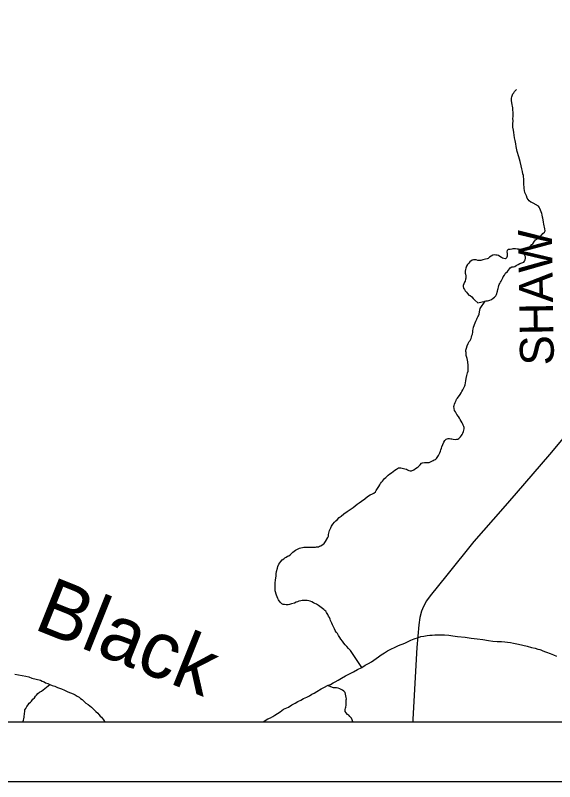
# Model space of a CAD drawing. Extents: x 10.6 to 44.6, y -2.6 to 23.4.
# Drawn here: x 14.367 to 15.273, y 15.426 to 16.714 of the extents above; entities that cross this region are included whole.
import ezdxf

# ---------------------------------------------------------------- set-up
doc = ezdxf.new("R2010")
doc.units = 0
for name, color, linetype in [('GM_X_County', 7, 'Continuous'), ('GM_X_Minor_Lake', 7, 'Continuous'), ('GM_X_Minor_River', 7, 'Continuous'), ('GM_X_Minor_River_Text', 7, 'Continuous'), ('GM_X_Township', 7, 'Continuous'), ('GM_X_Township_Road', 7, 'Continuous'), ('GM_X_Township_Road_Text', 7, 'Continuous'), ('SH_Data', 7, 'Continuous')]:
    doc.layers.add(name, color=color, linetype=linetype)

msp = doc.modelspace()

# ---------------------------------------------------------------- linework, layer by layer
at = {"layer": 'GM_X_County'}
msp.add_lwpolyline([(20.0033, 15.5302), (20.0033, 22.3267), (13.2033, 22.3267), (13.2033, 15.5267), (19.8413, 15.5267)], dxfattribs=at)
at = {"layer": 'GM_X_Minor_Lake'}
for points in [[(15.1779, 16.255), (15.1782, 16.2573), (15.1786, 16.2596), (15.1793, 16.2615), (15.1804, 16.2634), (15.1815, 16.2653), (15.1826, 16.2673), (15.1844, 16.2707), (15.1855, 16.2727), (15.1862, 16.2746), (15.1881, 16.2773), (15.1903, 16.2804), (15.1932, 16.2835), (15.1951, 16.2858), (15.1966, 16.2877), (15.198, 16.2897), (15.2007, 16.2913), (15.2033, 16.2913), (15.2056, 16.2918), (15.2082, 16.2933), (15.2116, 16.2953), (15.2142, 16.2969), (15.2173, 16.2977), (15.221, 16.299), (15.2221, 16.3009), (15.2229, 16.3028), (15.2236, 16.3055), (15.2235, 16.3082), (15.2227, 16.31), (15.2219, 16.3123), (15.2207, 16.3149), (15.2187, 16.3179), (15.2168, 16.319), (15.2141, 16.3201), (15.2118, 16.3208), (15.2095, 16.3211), (15.2068, 16.3215), (15.2049, 16.3214), (15.2026, 16.3214), (15.2008, 16.3209), (15.1977, 16.3205), (15.1947, 16.3204), (15.1928, 16.3185), (15.1925, 16.3162), (15.1926, 16.3135), (15.1926, 16.3112), (15.1927, 16.309), (15.192, 16.3063), (15.1901, 16.3047), (15.1874, 16.3054), (15.1851, 16.3058), (15.1832, 16.3068), (15.1805, 16.3087), (15.1782, 16.3102), (15.1759, 16.3109), (15.1736, 16.3108), (15.1709, 16.3111), (15.169, 16.3107), (15.166, 16.3091), (15.1634, 16.3075), (15.1612, 16.3052), (15.1593, 16.3048), (15.1566, 16.304), (15.154, 16.3035), (15.1517, 16.3031), (15.1487, 16.3019), (15.1468, 16.3018), (15.1437, 16.3021), (15.141, 16.3028), (15.1384, 16.3028), (15.1361, 16.3031), (15.1338, 16.3023), (15.1301, 16.2995), (15.1286, 16.2976), (15.126, 16.2949), (15.1245, 16.2922), (15.1235, 16.2887), (15.1228, 16.2868), (15.1225, 16.2838), (15.1221, 16.2807), (15.123, 16.2788), (15.1234, 16.2762), (15.1235, 16.2724), (15.1231, 16.2705), (15.1225, 16.2674), (15.1214, 16.2655), (15.1203, 16.2628), (15.1192, 16.2601), (15.1192, 16.2582), (15.1197, 16.2555), (15.1213, 16.2529), (15.1224, 16.251), (15.1248, 16.2488), (15.1264, 16.2462), (15.1283, 16.2439), (15.1306, 16.2429), (15.1337, 16.2406), (15.1357, 16.238), (15.1388, 16.2351), (15.1435, 16.231), (15.156, 16.2335)], [(15.156, 16.2335), (15.1578, 16.234), (15.1597, 16.234), (15.162, 16.2344), (15.1639, 16.2353), (15.1665, 16.2365), (15.1695, 16.2384), (15.1718, 16.24), (15.1736, 16.2423), (15.1751, 16.245), (15.1765, 16.2504), (15.1772, 16.2531), (15.1779, 16.255)]]:
    msp.add_lwpolyline(points, dxfattribs=at)
at = {"layer": 'GM_X_Minor_River'}
for points in [[(15.2187, 16.3179), (15.2322, 16.3262), (15.2341, 16.3286), (15.2359, 16.3301), (15.2385, 16.3344), (15.2407, 16.3363), (15.2437, 16.3387), (15.2456, 16.3402), (15.2482, 16.3418), (15.2512, 16.3449), (15.253, 16.3473), (15.2553, 16.3496), (15.2567, 16.3519), (15.2563, 16.3553), (15.2555, 16.358), (15.255, 16.3602), (15.2546, 16.3629), (15.2541, 16.3663), (15.2533, 16.3701), (15.2528, 16.3727), (15.2524, 16.3746), (15.2519, 16.3784), (15.2508, 16.3807), (15.2499, 16.3837), (15.2491, 16.3864), (15.2479, 16.3894), (15.2467, 16.3913), (15.2455, 16.3931), (15.2367, 16.3979), (15.2344, 16.399), (15.2324, 16.3997), (15.2297, 16.4023), (15.2281, 16.4041), (15.2266, 16.4068), (15.2253, 16.4106), (15.2237, 16.4139), (15.2225, 16.4162), (15.2221, 16.4196), (15.2216, 16.4226), (15.2216, 16.4257), (15.2211, 16.4287), (15.221, 16.4321), (15.221, 16.4352), (15.2209, 16.4371), (15.2209, 16.4394), (15.2204, 16.442), (15.22, 16.4447), (15.2192, 16.4477), (15.2187, 16.4515), (15.2174, 16.456), (15.2166, 16.4606), (15.2145, 16.4681), (15.2124, 16.4761), (15.2099, 16.4852), (15.2082, 16.4935), (15.2074, 16.498), (15.2065, 16.5033), (15.2052, 16.5079), (15.2044, 16.5124), (15.2039, 16.5166), (15.2034, 16.5208), (15.2025, 16.5257), (15.2024, 16.5314), (15.2027, 16.5364), (15.2026, 16.5402), (15.2029, 16.544), (15.2032, 16.5478), (15.2031, 16.5508), (15.2026, 16.5546), (15.2026, 16.5565), (15.2022, 16.5584), (15.2017, 16.5611), (15.2013, 16.5633), (15.2004, 16.5706), (15.2003, 16.5725), (15.2003, 16.5747), (15.2006, 16.5766), (15.2013, 16.5786), (15.2024, 16.5816), (15.2039, 16.5836), (15.2054, 16.5855), (15.2076, 16.5882), (15.2087, 16.589)], [(15.1184, 16.0116), (15.1195, 16.0147), (15.1202, 16.017), (15.1205, 16.0193), (15.1205, 16.0212), (15.1201, 16.0231), (15.1192, 16.025), (15.1181, 16.0272), (15.1173, 16.0291), (15.1157, 16.0321), (15.1141, 16.0347), (15.1125, 16.037), (15.1109, 16.0396), (15.1082, 16.0433), (15.107, 16.0456), (15.1058, 16.0479), (15.1046, 16.0501), (15.1038, 16.0535), (15.1033, 16.0565), (15.1036, 16.0585), (15.1044, 16.0608), (15.1054, 16.0634), (15.1069, 16.0665), (15.108, 16.0688), (15.1094, 16.0708), (15.1139, 16.077), (15.1153, 16.0793), (15.1168, 16.082), (15.1183, 16.0847), (15.1197, 16.087), (15.1208, 16.0893), (15.1215, 16.0912), (15.1223, 16.0931), (15.1226, 16.0962), (15.1232, 16.0996), (15.1239, 16.1034), (15.1249, 16.1088), (15.1264, 16.113), (15.1271, 16.1161), (15.1274, 16.1191), (15.1273, 16.1218), (15.1272, 16.1244), (15.1272, 16.1271), (15.1267, 16.1298), (15.1267, 16.1317), (15.1263, 16.1343), (15.1254, 16.1373), (15.125, 16.1392), (15.1238, 16.1423), (15.1237, 16.1445), (15.1237, 16.1472), (15.1236, 16.1491), (15.1236, 16.151), (15.1243, 16.1548), (15.1257, 16.1587), (15.1271, 16.1625), (15.129, 16.1656), (15.1308, 16.1675), (15.1323, 16.1706), (15.133, 16.1733), (15.1337, 16.176), (15.1344, 16.1783), (15.1351, 16.1813), (15.1354, 16.184), (15.1357, 16.1867), (15.1364, 16.1897), (15.1389, 16.1974), (15.1404, 16.2001), (15.1418, 16.2032), (15.1425, 16.2051), (15.1436, 16.207), (15.1447, 16.2089), (15.1458, 16.2116), (15.1465, 16.2154), (15.1468, 16.2185), (15.1475, 16.2212), (15.156, 16.2335)], [(14.8856, 15.8267), (14.8878, 15.8298), (14.8918, 15.8364), (14.8925, 15.839), (14.8929, 15.8417), (14.8932, 15.844), (14.8939, 15.8463), (14.8942, 15.8482), (14.8953, 15.8505), (14.8964, 15.8528), (14.8979, 15.8559), (14.9001, 15.859), (14.9027, 15.8621), (14.9053, 15.8648), (14.9075, 15.8664), (14.9109, 15.8699), (14.9142, 15.8726), (14.9187, 15.8762), (14.9239, 15.8801), (14.9307, 15.8848), (14.9341, 15.8872), (14.9374, 15.8895), (14.9408, 15.8923), (14.9445, 15.8946), (14.9483, 15.8978), (14.9535, 15.9017), (14.9584, 15.9052), (14.9629, 15.908), (14.9666, 15.91), (14.9689, 15.9112), (14.9715, 15.9135), (14.973, 15.9158), (14.9748, 15.9189), (14.977, 15.922), (14.9788, 15.9251), (14.9803, 15.9274), (14.9818, 15.9293), (14.9833, 15.9313), (14.9851, 15.9336), (14.987, 15.9356), (14.9888, 15.9375), (14.9911, 15.9395), (14.9929, 15.9414), (14.9955, 15.9437), (14.9985, 15.9453), (15.0012, 15.9477), (15.0042, 15.9496), (15.0068, 15.9512), (15.0087, 15.9524), (15.0105, 15.9536), (15.0143, 15.9537), (15.0163, 15.9533), (15.0189, 15.9526), (15.0212, 15.9519), (15.0235, 15.9512), (15.0255, 15.9501), (15.0278, 15.949), (15.0297, 15.9483), (15.032, 15.9484), (15.0361, 15.9504), (15.0387, 15.9523), (15.0414, 15.9539), (15.0432, 15.9551), (15.0451, 15.9567), (15.0466, 15.9586), (15.0488, 15.9613), (15.0507, 15.9621), (15.0541, 15.9626), (15.0571, 15.9623), (15.0598, 15.9623), (15.0617, 15.9624), (15.064, 15.9636), (15.0662, 15.9648), (15.0685, 15.966), (15.0704, 15.9668), (15.0722, 15.9676), (15.0741, 15.9691), (15.0763, 15.9726), (15.0774, 15.9745), (15.0785, 15.9765), (15.0796, 15.9788), (15.0807, 15.9815), (15.0814, 15.9841), (15.0825, 15.9864), (15.0832, 15.9891), (15.0864, 15.9968), (15.0879, 15.9995), (15.0905, 16.0018), (15.0939, 16.0027), (15.0962, 16.0027), (15.0981, 16.0024), (15.1, 16.0021), (15.1023, 16.0017), (15.1053, 16.0014), (15.108, 16.0015), (15.1099, 16.0019), (15.1118, 16.0027), (15.1147, 16.0058), (15.1162, 16.0078), (15.1173, 16.0097), (15.1184, 16.0116)], [(14.949, 15.6185), (14.9297, 15.647), (14.9265, 15.6503), (14.9234, 15.6533), (14.9207, 15.6563), (14.9183, 15.6593), (14.916, 15.6623), (14.9136, 15.6656), (14.9117, 15.6686), (14.9097, 15.672), (14.9077, 15.6754), (14.9057, 15.6776), (14.9042, 15.6802), (14.903, 15.6829), (14.9006, 15.6874), (14.8994, 15.69), (14.8982, 15.6927), (14.8974, 15.6949), (14.8962, 15.6972), (14.8954, 15.6995), (14.8942, 15.7021), (14.893, 15.7043), (14.8918, 15.707), (14.8906, 15.7089), (14.8894, 15.7107), (14.8882, 15.7126), (14.8863, 15.7141), (14.8847, 15.7159), (14.8762, 15.7226), (14.8727, 15.7244), (14.87, 15.7259), (14.8673, 15.727), (14.8646, 15.7284), (14.8619, 15.7295), (14.8596, 15.7302), (14.857, 15.7305), (14.8535, 15.7308), (14.8516, 15.7308), (14.8486, 15.7307), (14.8463, 15.7303), (14.8429, 15.7295), (14.8407, 15.7286), (14.8384, 15.7278), (14.8354, 15.7262), (14.8305, 15.725), (14.8271, 15.7241), (14.8248, 15.7237), (14.8217, 15.7236), (14.8191, 15.724), (14.8164, 15.7243), (14.8141, 15.7254), (14.8114, 15.728), (14.809, 15.7317), (14.8078, 15.7344), (14.8066, 15.737), (14.8054, 15.7396), (14.8033, 15.7468), (14.8032, 15.7514), (14.8031, 15.7556), (14.8034, 15.7605), (14.8037, 15.7651), (14.8046, 15.7723), (14.805, 15.7758), (14.8056, 15.7792), (14.807, 15.785), (14.8077, 15.7876), (14.8091, 15.7918), (14.811, 15.7942), (14.8125, 15.7965), (14.8151, 15.7988), (14.8177, 15.8008), (14.8196, 15.8024), (14.8218, 15.8036), (14.8241, 15.8051), (14.8263, 15.8059), (14.8282, 15.8075), (14.8304, 15.8095), (14.8327, 15.8118), (14.8353, 15.8138), (14.8375, 15.8153), (14.8398, 15.8165), (14.8417, 15.8177), (14.8443, 15.8189), (14.8462, 15.8193), (14.8488, 15.8198), (14.8515, 15.8202), (14.8553, 15.8203), (14.8591, 15.8204), (14.8641, 15.8201), (14.8682, 15.8202), (14.8709, 15.8203), (14.8728, 15.8207), (14.8758, 15.8211), (14.8777, 15.8219), (14.8796, 15.8228), (14.8837, 15.8255), (14.8856, 15.8267)], [(14.7829, 15.5267), (14.7866, 15.5292), (14.7911, 15.5319), (14.7953, 15.5339), (14.799, 15.5359), (14.8028, 15.5379), (14.8069, 15.5407), (14.8118, 15.5438), (14.8174, 15.5481), (14.8257, 15.5517), (14.8313, 15.5553), (14.8366, 15.5581), (14.8414, 15.5609), (14.8463, 15.5636), (14.8508, 15.566), (14.8561, 15.5684), (14.8606, 15.5708), (14.8648, 15.5732), (14.8685, 15.5752), (14.873, 15.5779), (14.8805, 15.5823), (14.8858, 15.5851), (14.8911, 15.5879), (14.896, 15.5899), (14.9005, 15.5923), (14.9042, 15.5943), (14.9091, 15.597), (14.9147, 15.6002), (14.9211, 15.6042), (14.9279, 15.6074), (14.9347, 15.6109), (14.9414, 15.6149), (14.949, 15.6185), (14.9546, 15.622), (14.9602, 15.6252), (14.9647, 15.628), (14.9688, 15.6307), (14.9726, 15.6335), (14.9767, 15.6362), (14.9812, 15.6394), (14.9868, 15.6426), (14.9921, 15.6461), (14.9973, 15.6489), (15.0049, 15.6525), (15.0101, 15.6553), (15.0207, 15.6593), (15.0312, 15.6641), (15.0369, 15.6665), (15.0441, 15.6686), (15.0478, 15.6702), (15.0531, 15.6711), (15.0585, 15.672), (15.063, 15.6725), (15.0668, 15.6725), (15.0714, 15.673), (15.0763, 15.6731), (15.0816, 15.6733), (15.0877, 15.673), (15.0946, 15.6724), (15.1018, 15.6714), (15.1095, 15.6705), (15.1224, 15.6693), (15.1324, 15.6676), (15.1423, 15.6663), (15.1522, 15.665), (15.1614, 15.6637), (15.169, 15.6627), (15.1763, 15.6621), (15.1831, 15.6619), (15.1888, 15.6616), (15.1934, 15.661)], [(15.1934, 15.661), (15.1984, 15.66), (15.2037, 15.6589), (15.2121, 15.6576), (15.2194, 15.6555), (15.2267, 15.6538), (15.2336, 15.652), (15.2397, 15.6506), (15.2443, 15.6492), (15.2477, 15.6485), (15.2496, 15.6478), (15.2519, 15.6467), (15.2554, 15.6453), (15.2589, 15.6438), (15.265, 15.6417), (15.2704, 15.6395), (15.2757, 15.6374)], [(14.3659, 15.6071), (14.372, 15.6057), (14.3781, 15.6047), (14.3843, 15.6037), (14.3892, 15.6027), (14.3942, 15.6005), (14.4088, 15.5967), (14.4118, 15.5952), (14.4149, 15.5941), (14.4176, 15.5927), (14.4211, 15.5912), (14.4245, 15.5898), (14.4288, 15.588), (14.433, 15.5866), (14.4376, 15.5848), (14.4441, 15.5822), (14.4495, 15.5801), (14.4549, 15.5775), (14.4595, 15.5757), (14.4637, 15.5739), (14.4672, 15.5721), (14.4706, 15.5699), (14.4737, 15.5685), (14.4764, 15.5662), (14.4791, 15.5644), (14.4819, 15.5618), (14.485, 15.5584), (14.4888, 15.5562), (14.4916, 15.5536), (14.4947, 15.5514), (14.497, 15.5496), (14.4993, 15.5473), (14.502, 15.5444), (14.5051, 15.5418), (14.5071, 15.5392), (14.5091, 15.5365), (14.5114, 15.5347), (14.513, 15.5328), (14.5149, 15.5306), (14.5165, 15.5276), (14.5172, 15.5267)], [(14.3792, 15.5267), (14.3806, 15.5298), (14.3809, 15.5321), (14.3816, 15.5348), (14.3823, 15.5413), (14.3826, 15.5435), (14.3829, 15.547), (14.3844, 15.5493), (14.3862, 15.5528), (14.388, 15.5555), (14.3899, 15.5582), (14.3921, 15.5601), (14.394, 15.5617), (14.3962, 15.5648), (14.3988, 15.5675), (14.4006, 15.5698), (14.4021, 15.5718), (14.4043, 15.5745), (14.4073, 15.5768), (14.4096, 15.578), (14.4107, 15.5784), (14.4245, 15.5898)], [(14.9336, 15.5267), (14.9335, 15.5268), (14.9331, 15.5287), (14.9327, 15.5306), (14.9311, 15.5332), (14.9288, 15.5362), (14.9268, 15.5381), (14.9249, 15.5392), (14.9225, 15.5422), (14.921, 15.5444), (14.9209, 15.5475), (14.9212, 15.5497), (14.9219, 15.5517), (14.9222, 15.5551), (14.9226, 15.557), (14.9225, 15.5589), (14.9225, 15.5612), (14.9224, 15.5639), (14.9228, 15.5658), (14.9223, 15.568), (14.9219, 15.5707), (14.9214, 15.5733), (14.921, 15.576), (14.9183, 15.5786), (14.916, 15.5804), (14.914, 15.5815), (14.9117, 15.5826), (14.909, 15.5833), (14.906, 15.584), (14.9037, 15.584), (14.901, 15.5843), (14.8911, 15.5879)]]:
    msp.add_lwpolyline(points, dxfattribs=at)
at = {"layer": 'GM_X_Township'}
msp.add_lwpolyline([(13.2033, 20.8217), (13.2033, 15.5267), (15.2903, 15.5267)], dxfattribs=at)
at = {"layer": 'GM_X_Township_Road'}
msp.add_lwpolyline([(15.2973, 16.0158), (15.2954, 16.0136), (15.2638, 15.976), (15.2082, 15.9112), (15.1857, 15.8854), (15.1368, 15.8297), (15.0914, 15.7734), (15.0636, 15.7386), (15.0576, 15.7303), (15.0524, 15.7206), (15.0492, 15.713), (15.0463, 15.7024), (15.0443, 15.6899), (15.0409, 15.6519), (15.0344, 15.5314), (15.0343, 15.5267)], dxfattribs=at)
at = {"layer": 'SH_Data'}
msp.add_line((13.1028, 15.4265), (20.1028, 15.4265), dxfattribs=at)

# ---------------------------------------------------------------- texts
at = {"layer": 'GM_X_Minor_River_Text'}
msp.add_text('Black', height=0.09475, rotation=338.2008, dxfattribs=at).set_placement((14.3952, 15.6838))
at = {"layer": 'GM_X_Township_Road_Text'}
msp.add_text('SHAW', height=0.05682, rotation=90.9362, dxfattribs=at).set_placement((15.2715, 16.126))

doc.saveas('drawing.dxf')
